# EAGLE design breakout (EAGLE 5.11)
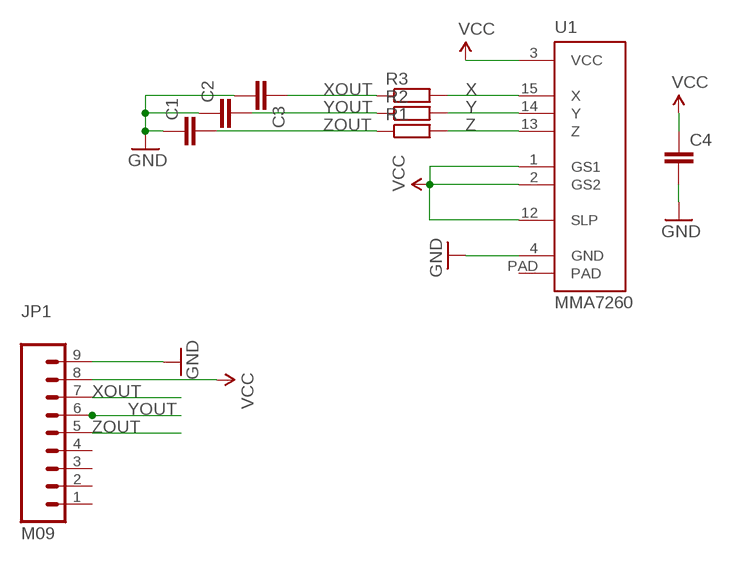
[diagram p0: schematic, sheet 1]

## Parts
C1  C-EU025-025X050  [C025-025X050]
C2  C-EU025-025X050  [C025-025X050]
C3  C-EU025-025X050  [C025-025X050]
C4  C-EU025-025X050  [C025-025X050]
JP1  M09  [1X09]
R1  R-EU_0204/7  [0204/7]
R2  R-EU_0204/7  [0204/7]
R3  R-EU_0204/7  [0204/7]
U1  MMA7260  [MMA7260]

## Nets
GND: C1.1 C2.1 C3.2 C4.2 JP1.9 U1.4(GND)
VCC: C4.1 JP1.8 U1.1(GS1) U1.2(GS2) U1.3(VCC) U1.12(SLP)
X: R3.2 U1.15(X)
XOUT: C3.1 JP1.7 R3.1
Y: R2.2 U1.14(Y)
YOUT: C2.2 JP1.6 R2.1
Z: R1.2 U1.13(Z)
ZOUT: C1.2 JP1.5 R1.1
Unconnected: JP1.1 JP1.2 JP1.3 JP1.4 U1.PAD

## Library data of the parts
C1-C4 = rcl:C-EU: CAPACITOR, European symbol
JP1 = SparkFun:M09: Header 9 Standard 9-pin 0.1" header. Use with straight break away headers (SKU : PRT-00116), right angle break away headers (PRT-00553), swiss pins (PRT-00743), machine pins (PRT-00117), and female headers (PRT-00115).
R1-R3 = resistor:R-EU_: RESISTOR, European symbol
U1 = SparkFun:MMA7260: MMA7260Q Triple axis accelerometer from Freescale. Schematic element and footprint production proven. Center pad has reduced paste layer for solder short reduction. Spark Fun Electronics SKU : COM-00308

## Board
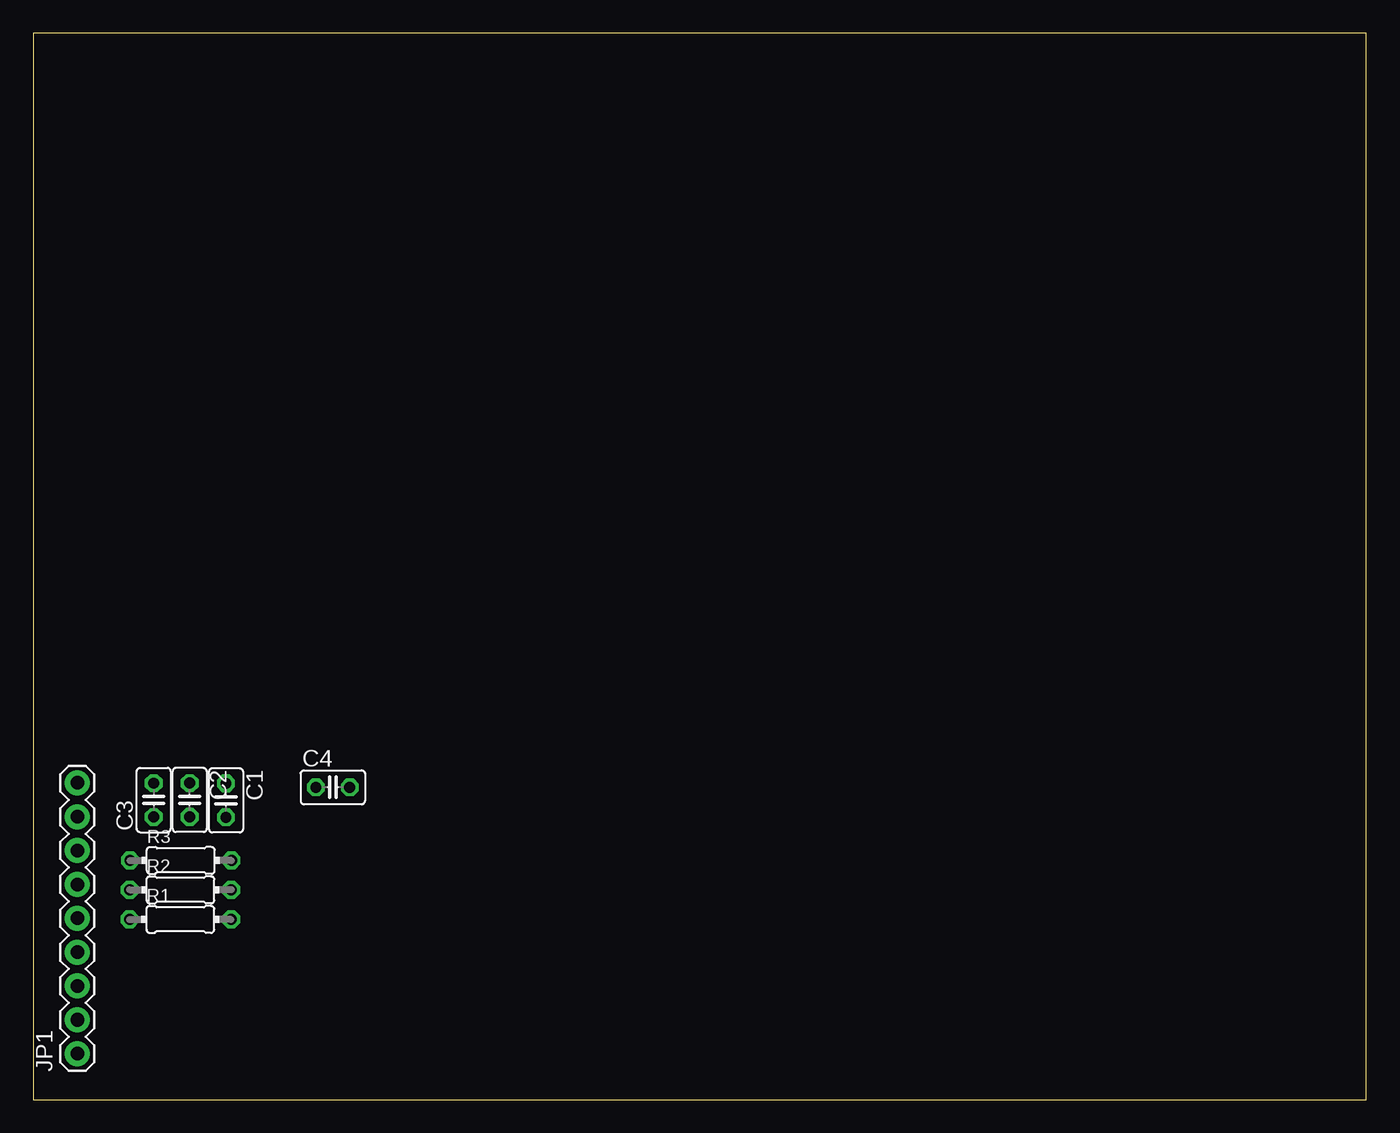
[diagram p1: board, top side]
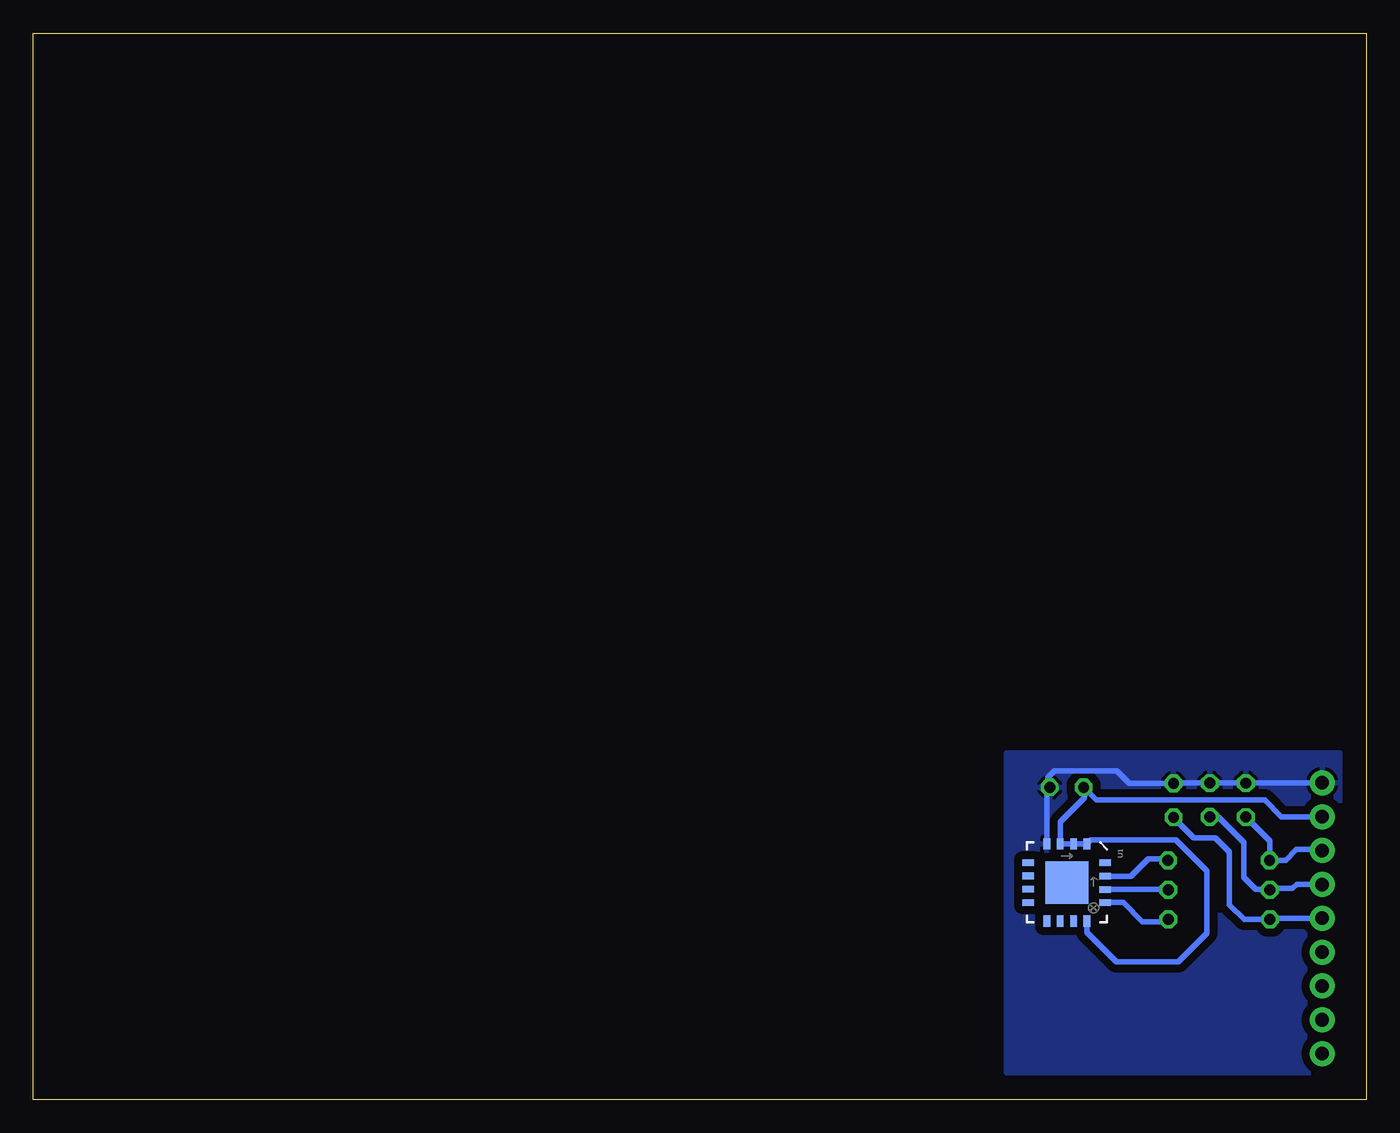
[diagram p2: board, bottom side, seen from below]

Size 100 x 80 mm. Coordinates in mm from the lower left corner, seen from the top.
Outline: 0,0 100,0 100,80 0,80 0,0
Copper layers (1*16): Top 0.035mm / dielectric 1.5mm / Bottom 0.035mm
Design rules "default": minimum track width 10mil, minimum drill 24mil, track to track 8mil, track to pad 8mil, pad to pad 8mil, via to via 8mil, smd to smd 8mil, copper to edge 40mil, drill to drill 8mil, minimum pad ring 10mil, minimum via ring 8mil, stop-mask expansion 4mil, vias tented up to drill 0mil, thermal gap 10mil

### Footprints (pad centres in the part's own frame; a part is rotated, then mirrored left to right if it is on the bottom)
C025-025X050 = drill 0.813 octagon: 1 -1.27,0; 2 1.27,0
1X09 = drill 1.016 pad 1.88 round: 1 0,0; 2 2.54,0; 3 5.08,0; 4 7.62,0; 5 10.16,0; 6 12.7,0; 7 15.24,0; 8 17.78,0; 9 20.32,0
0204/7 = drill 0.813 octagon: 1 -3.81,0; 2 3.81,0
MMA7260 = smd 0.855 x 0.5: 1 -2.902,1.5; 2 -2.902,0.5; 3 -2.902,-0.5; 4 -2.902,-1.5; 9 2.902,-1.5; 10 2.902,-0.5; 11 2.902,0.5; 12 2.902,1.5 | smd 0.5 x 0.855: 5 -1.5,-2.902; 6 -0.5,-2.902; 7 0.5,-2.902; 8 1.5,-2.902; 13 1.5,2.877; 14 0.525,2.877; 15 -0.475,2.877; 16 -1.5,2.877 | smd 3.2 x 3.2: PAD 0,0

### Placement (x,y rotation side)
C1  14.46,22.45 270 top
C2  11.73,22.48 270 top
C3  9.03,22.47 90 top
C4  22.47,23.43 0 top
JP1  3.3,3.44 90 top
R1  11.03,13.52 0 top
R2  11.04,15.73 0 top
R3  11.06,17.94 0 top
U1  22.45,16.28 270 bottom

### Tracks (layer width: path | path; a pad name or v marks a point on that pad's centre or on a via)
GND
  Bottom 0.406: U1.4 23.95,23.01 23.74,23.22 C4.2 23.88,23.57 23.88,24.19 23.4,24.66 18.7,24.66 17.76,23.72 C1.1 14.43,23.75 C2.1 C3.2 9.01,23.76 JP1.9
  pour Bottom (isolate 0.61): 25,26 2,26 2,2 27,2 27,26
VCC
  Bottom 0.406: JP1.8 6.35,21.22 7.6,22.46 20.24,22.46 C4.1 21.16,23.38 21.16,22.62 22.95,20.82 U1.3 U1.2 U1.1 20.65,19.48 14.28,19.48 11.95,17.14 11.95,12.47 14.09,10.34 18.75,10.34 20.95,12.54 U1.12
X
  Bottom 0.406: U1.15 17.64,16.75 16.35,18.04 14.97,18.04 R3.2
XOUT
  Bottom 0.406: JP1.7 3.37,18.75 5.23,18.75 6.04,17.94 R3.1 7.25,19.42 C3.1
Y
  Bottom 0.406: U1.14 14.87,15.75 R2.2
YOUT
  Bottom 0.406: JP1.6 5.21,16.14 5.53,15.83 7.13,15.83 R2.1 7.25,15.76 8.28,15.76 9.2,16.68 9.2,19.3 11.1,21.21 C2.2
Z
  Bottom 0.406: U1.13 18.23,14.78 16.78,13.34 15.02,13.34 R1.2
ZOUT
  Bottom 0.406: JP1.5 7.14,13.6 R1.1 9.15,13.52 10.26,14.62 10.26,18.58 11.32,19.65 12.93,19.65 C1.2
